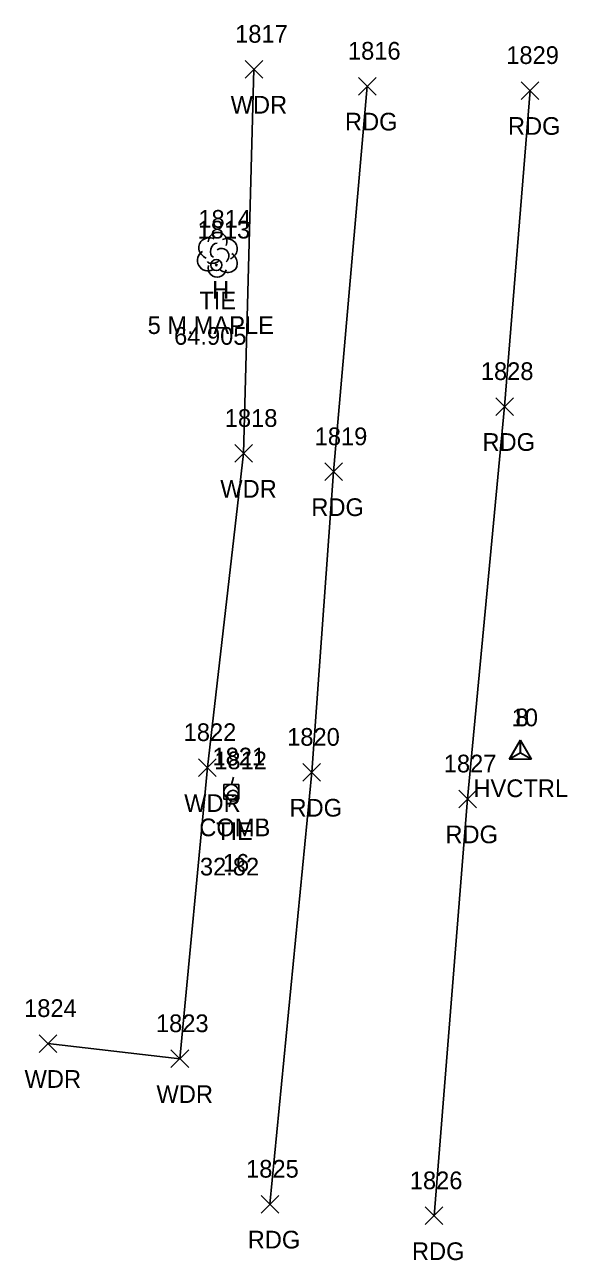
# Model space of a CAD drawing. Extents: x 1469310 to 1475157, y 493997 to 498873.
# Drawn here: x 1469571.6 to 1469632.9, y 497604.9 to 497744.4 of the extents above; entities that cross this region are included whole.
import ezdxf

# ---------------------------------------------------------------- set-up
doc = ezdxf.new("R2010")
doc.units = 0
for name, color, linetype in [('C_A', 7, 'Continuous'), ('C_C', 7, 'Continuous'), ('C_I', 7, 'Continuous'), ('CBP', 7, 'Continuous'), ('CPSM', 7, 'Continuous'), ('L_A', 7, 'Continuous'), ('L_C', 7, 'Continuous'), ('L_I', 7, 'Continuous'), ('L_TIC', 7, 'Continuous'), ('LAWA', 7, 'Continuous'), ('LTD', 7, 'Continuous'), ('P_A', 7, 'Continuous'), ('P_I', 7, 'Continuous'), ('P_TIC', 7, 'Continuous'), ('PEU', 7, 'Continuous'), ('U_A', 7, 'Continuous'), ('U_C', 7, 'Continuous'), ('U_I', 7, 'Continuous'), ('UP', 7, 'Continuous')]:
    doc.layers.add(name, color=color, linetype=linetype)

msp = doc.modelspace()

# ---------------------------------------------------------------- linework, layer by layer
at = {"layer": 'CBP'}
for centre, radius in [((1469593.26, 497717.3), 0.625), ((1469593.26, 497717.3), 0.0833), ((1469595.14, 497657.37), 0.625), ((1469595.14, 497657.37), 0.0833)]:
    msp.add_circle(centre, radius, dxfattribs=at)
at = {"layer": 'CPSM'}
for p, q in [((1469626.36, 497661.49), (1469627.61, 497663.66)), ((1469626.37, 497661.5), (1469627.62, 497663.66)), ((1469628.86, 497661.49), (1469627.61, 497663.66)), ((1469627.61, 497662.22), (1469627.61, 497663.66)), ((1469628.87, 497661.5), (1469627.62, 497663.66)), ((1469627.62, 497662.22), (1469627.62, 497663.66)), ((1469626.36, 497661.49), (1469627.61, 497662.22)), ((1469626.36, 497661.49), (1469628.86, 497661.49)), ((1469626.37, 497661.5), (1469627.62, 497662.22)), ((1469626.37, 497661.5), (1469628.87, 497661.5)), ((1469627.61, 497662.22), (1469627.61, 497662.22)), ((1469627.61, 497662.22), (1469628.86, 497661.49)), ((1469627.62, 497662.22), (1469627.62, 497662.22)), ((1469627.62, 497662.22), (1469628.87, 497661.5))]:
    msp.add_line(p, q, dxfattribs=at)
at = {"layer": 'L_TIC'}
for points in [[(1469596.5, 497738.41), (1469598.5, 497740.41)], [(1469598.5, 497738.41), (1469596.5, 497740.41)], [(1469595.33, 497695.03), (1469597.33, 497697.03)], [(1469597.33, 497695.03), (1469595.33, 497697.03)], [(1469591.25, 497659.55), (1469593.25, 497661.55)], [(1469593.25, 497659.55), (1469591.25, 497661.55)], [(1469573.22, 497628.39), (1469575.22, 497630.39)], [(1469575.22, 497628.39), (1469573.22, 497630.39)], [(1469588.13, 497626.68), (1469590.13, 497628.68)], [(1469590.13, 497626.68), (1469588.13, 497628.68)]]:
    msp.add_lwpolyline(points, dxfattribs=at)
at = {"layer": 'LAWA'}
msp.add_lwpolyline([(1469597.5, 497739.41), (1469596.33, 497696.03), (1469592.25, 497660.55), (1469589.13, 497627.68), (1469574.22, 497629.39)], dxfattribs=at)
at = {"layer": 'LTD'}
msp.add_line((1469593.35, 497718.52), (1469593.35, 497718.52), dxfattribs=at)
msp.add_line((1469593.35, 497718.52), (1469593.35, 497718.52), dxfattribs=at)
msp.add_arc((1469593.4, 497719.95), 1.05, 335.5272, 180.9563, dxfattribs=at)
for centre, major_axis, ratio, start_param, end_param in [((1469592.56, 497719.18), (1.21, -0.51), 0.895232, 1.570796, 4.712389), ((1469594.39, 497719.1), (-1.14, -0.48), 0.949671, 1.570796, 4.712389), ((1469592.27, 497717.81), (0.58, -1.04), 0.959034, 3.141593, 6.283185), ((1469593.14, 497718.97), (-0.208, -0.792), 0.645439, 3.141593, 6.283185), ((1469593.85, 497718.35), (-0.5, 0.667), 0.989748, 3.141593, 6.283185), ((1469592.89, 497717.77), (-0.625, -0.083), 0.423636, 0, 3.141593), ((1469594.35, 497717.68), (-1.09, 0.79), 0.841452, 1.570796, 4.712389), ((1469593.35, 497717.02), (0.26, 1.06), 0.942809, 1.570796, 4.712389)]:
    msp.add_ellipse(centre, major_axis=major_axis, ratio=ratio, start_param=start_param, end_param=end_param, dxfattribs=at)
at = {"layer": 'P_TIC'}
for points in [[(1469609.31, 497736.5), (1469611.31, 497738.5)], [(1469611.31, 497736.5), (1469609.31, 497738.5)], [(1469627.72, 497736.01), (1469629.72, 497738.01)], [(1469629.72, 497736.01), (1469627.72, 497738.01)], [(1469624.84, 497700.32), (1469626.84, 497702.32)], [(1469626.84, 497700.32), (1469624.84, 497702.32)], [(1469605.5, 497692.96), (1469607.5, 497694.96)], [(1469607.5, 497692.96), (1469605.5, 497694.96)], [(1469603.03, 497659.02), (1469605.03, 497661.02)], [(1469605.03, 497659.02), (1469603.03, 497661.02)], [(1469620.65, 497656.01), (1469622.65, 497658.01)], [(1469622.65, 497656.01), (1469620.65, 497658.01)], [(1469598.31, 497610.25), (1469600.31, 497612.25)], [(1469600.31, 497610.25), (1469598.31, 497612.25)], [(1469616.87, 497608.94), (1469618.87, 497610.94)], [(1469618.87, 497608.94), (1469616.87, 497610.94)]]:
    msp.add_lwpolyline(points, dxfattribs=at)
at = {"layer": 'PEU'}
for points in [[(1469610.31, 497737.5), (1469606.5, 497693.96), (1469604.03, 497660.02), (1469599.31, 497611.25)], [(1469617.87, 497609.94), (1469621.65, 497657.01), (1469625.84, 497701.32), (1469628.72, 497737.01)]]:
    msp.add_lwpolyline(points, dxfattribs=at)
at = {"layer": 'UP'}
for p, q in [((1469595.2, 497659.47), (1469594.95, 497658.63)), ((1469594.11, 497656.97), (1469594.11, 497658.63)), ((1469594.11, 497658.63), (1469595.78, 497658.63)), ((1469594.95, 497657.8), (1469594.95, 497657.8)), ((1469595.78, 497658.63), (1469595.78, 497656.97)), ((1469595.78, 497656.97), (1469594.11, 497656.97)), ((1469594.7, 497656.13), (1469594.95, 497656.97))]:
    msp.add_line(p, q, dxfattribs=at)
msp.add_circle((1469594.95, 497657.8), 0.833, dxfattribs=at)

# ---------------------------------------------------------------- texts
at = {"layer": 'C_A'}
for s, p in [('TIE', (1469591.33, 497712.3)), ('HVCTRL', (1469622.31, 497657.22)), ('HVCTRL', (1469622.31, 497657.22)), ('TIE', (1469593.22, 497652.37))]:
    msp.add_text(s, height=2, dxfattribs=at).set_placement(p)
at = {"layer": 'C_C'}
for s, p in [('64.905', (1469588.48, 497708.3)), ('32.82', (1469591.4, 497648.37))]:
    msp.add_text(s, height=2, dxfattribs=at).set_placement(p)
at = {"layer": 'C_I'}
for s, p in [('1813', (1469591.13, 497720.3)), ('10', (1469626.63, 497665.22)), ('8', (1469627.05, 497665.22)), ('1812', (1469593.02, 497660.37))]:
    msp.add_text(s, height=2, dxfattribs=at).set_placement(p)
at = {"layer": 'L_A'}
for s, p in [('WDR', (1469594.87, 497734.41)), ('H', (1469592.78, 497713.52)), ('WDR', (1469593.7, 497691.03)), ('WDR', (1469589.62, 497655.55)), ('WDR', (1469571.58, 497624.39)), ('WDR', (1469586.49, 497622.68))]:
    msp.add_text(s, height=2, dxfattribs=at).set_placement(p)
at = {"layer": 'L_C'}
msp.add_text('5 M.MAPLE', height=2, dxfattribs=at).set_placement((1469585.49, 497709.52))
at = {"layer": 'L_I'}
for s, p in [('1817', (1469595.38, 497742.41)), ('1814', (1469591.22, 497721.52)), ('1818', (1469594.21, 497699.03)), ('1822', (1469589.56, 497663.55)), ('1824', (1469571.53, 497632.39)), ('1823', (1469586.43, 497630.68))]:
    msp.add_text(s, height=2, dxfattribs=at).set_placement(p)
at = {"layer": 'P_A'}
for p in [(1469607.79, 497732.5), (1469626.21, 497732.01), (1469623.33, 497696.32), (1469603.99, 497688.96), (1469601.52, 497655.02), (1469619.14, 497652.01), (1469596.8, 497606.25), (1469615.36, 497604.94)]:
    msp.add_text('RDG', height=2, dxfattribs=at).set_placement(p)
at = {"layer": 'P_I'}
for s, p in [('1816', (1469608.13, 497740.5)), ('1829', (1469626.02, 497740.01)), ('1828', (1469623.15, 497704.32)), ('1819', (1469604.37, 497696.96)), ('1820', (1469601.26, 497663.02)), ('1827', (1469618.96, 497660.01)), ('1825', (1469596.62, 497614.25)), ('1826', (1469615.12, 497612.94))]:
    msp.add_text(s, height=2, dxfattribs=at).set_placement(p)
at = {"layer": 'U_A'}
msp.add_text('COMB', height=2, dxfattribs=at).set_placement((1469591.33, 497652.8))
at = {"layer": 'U_C'}
msp.add_text('16', height=2, dxfattribs=at).set_placement((1469593.99, 497648.8))
at = {"layer": 'U_I'}
msp.add_text('1821', height=2, dxfattribs=at).set_placement((1469592.82, 497660.8))

doc.saveas('drawing.dxf')
